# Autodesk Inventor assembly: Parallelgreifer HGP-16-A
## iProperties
Shininess: 20.0
Length Units: 11269
Angle Units: 11279
Time Units: 11290
Mass Units: 11283
Length Display Precision: 3
Angle Display Precision: 2
Compacted: True
Part Number: Parallelgreifer HGP-16-A
Document SubType Name: Assembly
Created: 2003-05
Designer: KOPP
Density: 0.0
Volumn: 0.0
Area: 0.0
PropertySet Name: Model Information
Control State: 0
Master: False
Checked Out: False
Author: KOPP
